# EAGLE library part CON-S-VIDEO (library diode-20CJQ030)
Various Connectors for S-Video - CUI Inc
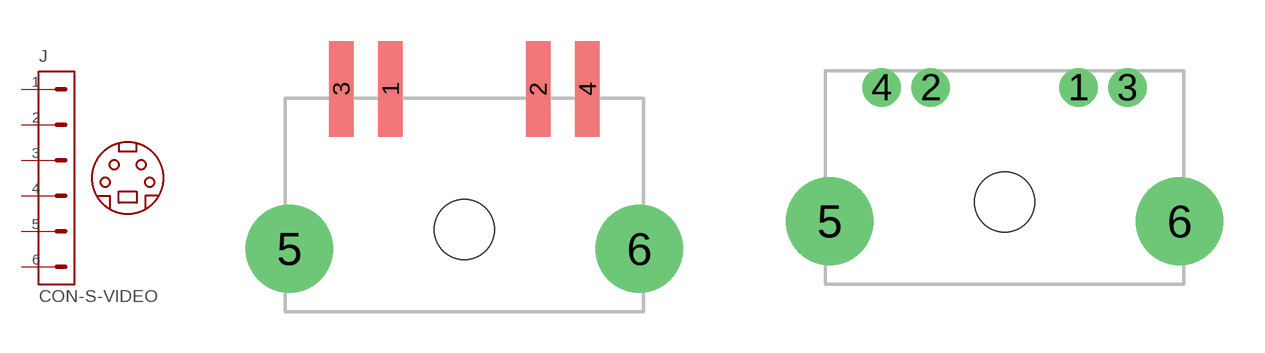
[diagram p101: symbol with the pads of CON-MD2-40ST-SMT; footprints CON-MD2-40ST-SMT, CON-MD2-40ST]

Designator prefix J

## CON-S-VIDEO-SMT  [CON-MD2-40ST-SMT]
1  1  pas
2  2  pas
3  3  pas
4  4  pas
5  SHIELD  pas
6  SHIELD  pas

## CON-S-VIDEO  [CON-MD2-40ST]
Pads as for CON-MD2-40ST-SMT

## Footprint CON-MD2-40ST-SMT (pad centres in mm)
CUI Inc's MD2-40ST MINIATURE CIRCULAR DIN CONNECTOR SPECIFICATIONS: RATING: 12V DC @ 2A; 100V AC @ 1A CONTACT RESISTANCE: 30m OHMS MAX INSULATION RESISTANCE: 50M OHMS MIN: 250V DC VOLTAGE WITHSTAND: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
smd 0.9 x 3.5: 1 -2.7,-1.75; 2 2.7,-1.75; 3 -4.5,-1.75; 4 4.5,-1.75
drill 2.2 pad 3 round: 5 -6.4,-7.6; 6 6.4,-7.6
hole 2.2 at 0,-6.9

## Footprint CON-MD2-40ST (pad centres in mm)
CUI Inc's MD2-40ST MINIATURE CIRCULAR DIN CONNECTOR SPECIFICATIONS: RATING: 12V DC @ 2A; 100V AC @ 1A CONTACT RESISTANCE: 30m OHMS MAX INSULATION RESISTANCE: 50M OHMS MIN: 250V DC VOLTAGE WITHSTAND: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
drill 0.9 round: 1 2.7,-0.6; 2 -2.7,-0.6; 3 4.5,-0.6; 4 -4.5,-0.6
drill 2.2 pad 3 round: 5 -6.4,-5.5; 6 6.4,-5.5
hole 2.2 at 0,-4.8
